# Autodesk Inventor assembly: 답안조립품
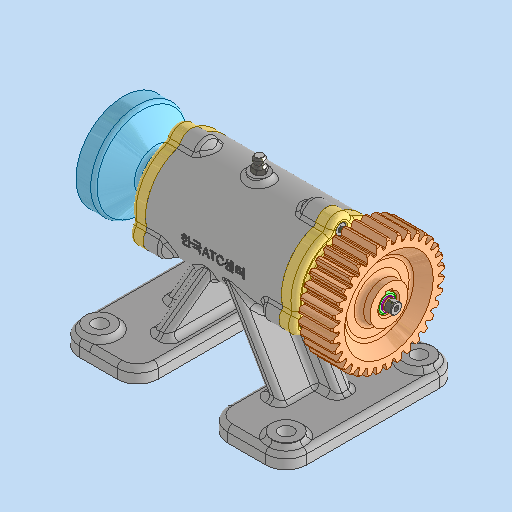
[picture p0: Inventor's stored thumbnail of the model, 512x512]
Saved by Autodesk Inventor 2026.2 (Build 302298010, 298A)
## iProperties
Created: 2026-04
Part Number: 답안조립품
Document SubType Name: Assembly
Designer: PC-2-03
Author: PC-2-03
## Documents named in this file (16)
- C:\Users\PC-2-03\Desktop\760403V1007\답안조립품.iam
- C:\Users\PC-2-03\Desktop\760403V1007\본체.ipt
- C:\Users\PC-2-03\Desktop\760403V1007\축.ipt
- C:\Users\PC-2-03\Desktop\760403V1007\커버.ipt
- C:\Users\PC-2-03\Desktop\760403V1007\오일 실 20 35 8.ipt
- C:\Users\PC-2-03\Desktop\760403V1007\깊은 홈 볼 베어링 6004.ipt
- C:\Users\PC-2-03\Desktop\760403V1007\스퍼 기어.ipt
- C:\Users\PC-2-03\Desktop\760403V1007\평행 키 4x4x14.ipt
- C:\Users\PC-2-03\Desktop\760403V1007\평 와셔 M4.ipt
- C:\Users\PC-2-03\Desktop\760403V1007\스프링 와셔 M4.ipt
- C:\Users\PC-2-03\Desktop\760403V1007\플러그 M6x0,75.ipt
- C:\Users\PC-2-03\Desktop\760403V1007\6각 구멍붙이 볼트 M4x12.ipt
- C:\Users\PC-2-03\Desktop\760403V1007\플랜지.ipt
- C:\Users\PC-2-03\Desktop\760403V1007\엔드 캡.ipt
- C:\Users\PC-2-03\Desktop\760403V1007\그리스 니플 M6x0,75.ipt
- C:\Users\PC-2-03\Desktop\760403V1007\실링.ipt
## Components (11 placed, 4 different names)
1. 6각 구멍붙이 볼트 M4x12:1
2. 플랜지:1
3. 6각 구멍붙이 볼트 M4x12:2
4. 그리스 니플 M6x0,75:1 — 각도:2
5. 플러그 M6x0,75:1
6. 6각 구멍붙이 볼트 M4x12:3
7. 6각 구멍붙이 볼트 M4x12:5
8. 6각 구멍붙이 볼트 M4x12:6
9. 6각 구멍붙이 볼트 M4x12:4
10. 6각 구멍붙이 볼트 M4x12:7
11. 6각 구멍붙이 볼트 M4x12:8
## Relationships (1: Angle 1)
- 각도:2 [Angle]: 그리스 니플 M6x0,75:1
